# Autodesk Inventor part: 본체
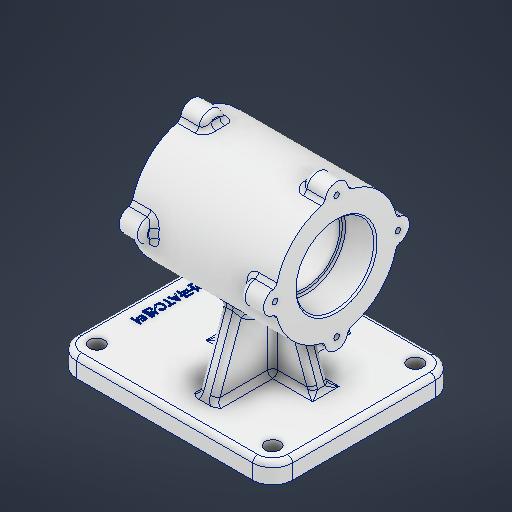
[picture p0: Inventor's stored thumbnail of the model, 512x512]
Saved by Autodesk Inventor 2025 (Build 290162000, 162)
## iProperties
Created: 2025-08
Part Number: 본체
Material: 알루미늄 6061
Document SubType Name: Modeling
Designer: infra006
Density: 2.7 g/cm^3
Appearance: 알루미늄 - 평지
Mass: 1231.61 g
Surface Area: 805.324 cm^2
Volume: 456.153 cm^3
Author: infra006
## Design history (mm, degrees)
sketch "스케치1"
  geometry: L1 (-43.5, 0)-(43.5, 0); L2 (43.5, 0)-(43.5, 23.5); L3 (43.5, 23.5)-(-43.5, 23.5); L4 (-43.5, 23.5)-(-43.5, 0); L5 (-43.5, 0)-(-24.5, 0); L6 (-24.5, 0)-(-24.5, 23.5); L7 (-24.5, 23.5)-(-43.5, 23.5); L8 (-43.5, 23.5)-(-43.5, 0); L9 (43.5, 0)-(24.5, 0); L10 (24.5, 0)-(24.5, 23.5); L11 (24.5, 23.5)-(43.5, 23.5); L12 (43.5, 23.5)-(43.5, 0); L13 (24.5, 0)-(-24.5, 0); L14 (-24.5, 0)-(-24.5, 21); L15 (-24.5, 21)-(24.5, 21); L16 (24.5, 21)-(24.5, 0); L17 (-43.5, 0)-(43.5, 0); L18 (43.5, 0)-(43.5, 37); L19 (43.5, 37)-(-43.5, 37); L20 (-43.5, 37)-(-43.5, 0); 6 further points
  constraints: 40 end point, 10 parallel, 5 horizontal, 5 perpendicular, 2 point on line, 1 coincident, 1 midpoint
  dimensions: "d1" = 87 distance of L3.end L2.end; "d2" = 19 distance of L7.end L6.end; "d3" = 23.5 distance of L6.end L5.end; "d4" = 23.5 distance of L1.end L2.end; "d5" = 19 distance of L10.end L11.end; "d6" = 21 distance of L13.end L14.end; "d7" = 37 distance of L18.end L17.end
revolve "회전1" sketch "스케치1" stored, may be unused: angle "d9" = 90 deg
sketch "스케치2"
  geometry: L1 (0, 0)-(0, -82); L2 (0, -82)-(60, -82); L3 (0, -82)-(-70, -82); L4 (-70, -82)-(-70, -70); L5 (-70, -70)-(60, -70); L6 (60, -70)-(60, -82)
  constraints: 12 end point, 2 horizontal, 2 perpendicular, 2 vertical
  dimensions: "d10" = 82 distance of L1.start L1.end; "d11" = 60 distance of L1.end L2.end; "d12" = 70 distance of L1.end L3.end; "d13" = 12 distance of L3.end L4.end
extrude "돌출1" join sketch "스케치2" stored distance "d14" = 110; taper "d15" = 0 deg
sketch "스케치3"
  geometry: L1 (0, 0)-(0, 110) reference; L2 (0, 0)-(130, 0) reference; L3 (130, 110)-(0, 110) reference; L4 (12, 98)-(118, 98); L5 (118, 98)-(118, 12); L6 (118, 12)-(12, 12); L7 (12, 12)-(12, 98)
  constraints: 8 end point, 2 parallel, 1 horizontal, 1 perpendicular
  dimensions: "d20" = 106 distance between parallel lines of L5 L7; "d21" = 86 distance between parallel lines of L6 L4; "d22" = 12 distance between parallel lines of L1 L7; "d23" = 12 distance between parallel lines of L3 L4
hole "구멍1" sketch "스케치3" at (12, 98), (12, 12), (118, 12), (118, 98) diameter "d24" = 9; stored, may be unused: countersink angle "d28" = 90 deg, drill point angle "d30" = 118 deg; dims "d25" = 6, "d26" = 4, "d27" = 2, "d29" = 12
sketch "스케치4"
  geometry: L1 (70, 50)-(80, 50); L2 (80, 50)-(80, 60); L3 (80, 60)-(70, 60); L4 (70, 60)-(70, 50); L5 (70, 50)-(80, 60); L6 (80, 50)-(70, 60); L7 (130, 110)-(130, 0) reference; L8 (130, 110)-(0, 110) reference; 1 further point
  constraints: 12 end point, 2 midpoint, 2 parallel, 1 horizontal, 1 perpendicular
  dimensions: "d31" = 10 distance of L3.end L2.end; "d32" = 10 distance of L2.end L1.end; "d125" = 55 distance from line of L7 point (75, 55); "d126" = 55 distance from line of L8 point (75, 55)
extrude "돌출2" join sketch "스케치4" stored distance "d33" = 110; taper "d34" = 0 deg
sketch "스케치5"
  geometry: L1 (0, -70)-(0, -36.661) reference; L2 (0, -70)-(-25, -70); L3 (-70, -70)-(60, -70) reference; L4 (-25, -70)-(-12.989, -37); L5 (43.5, -37)-(-43.5, -37) reference; L6 (10, -70)-(10, -36.661) reference; L7 (10, -70)-(35, -70); L8 (35, -70)-(22.989, -37); 1 further point
  constraints: 8 end point, 4 point on line
  dimensions: "d35" = 25 distance of L1.start L2.end; "d36" = 70 deg angle of L2 L4; "d37" = 25 distance of L6.start L7.end; "d38" = 70 deg angle of L8 L7; "d124" = 60 distance of L7.end L2.end (derived)
feature "리브1" dims "d39" = 1, "d40" = 10, "d41" = 0, "d42" = 0, "d43" = 1, "d44" = 1
feature "리브2" dims "d45" = 1, "d46" = 10, "d47" = 0, "d48" = 0, "d49" = 1, "d50" = 1
sketch "스케치7"
  geometry: C1 r 7 at (0, 37); C2 r 7 at (-37, 0); C3 r 7 at (0, -37); C4 r 7 at (37, 0); 10 further points
  constraints: 4 centre point, 1 horizontal alignment, 11 other
  dimensions: "d64" = 14 diameter of C1; "d67" = 360 deg dimension on point (0, 0) C1.centre (derived); "d69" = 37 distance of point (0, 0) C1.centre (derived); "d70" = 14 diameter of C2 (derived); "d71" = 37 distance of point (0, 0) C2.centre (derived)
extrude "돌출3" join sketch "스케치7" distance "d72" = 14; taper "d73" = 0 deg
sketch "스케치9"
  geometry: A1 r 37 centre (37, 0) between (0, 0) and (37, 37); 4 further points
  constraints: 4 point on circle, 2 coincident, 1 centre point
  dimensions: "d74" = 74 diameter of A1
hole "구멍3" sketch "스케치9" at (0, 0), (37, 37), (74, 0), (37, -37) diameter "d82" = 3.242; stored, may be unused: countersink angle "d86" = 90 deg, drill point angle "d88" = 118 deg; dims "d83" = 8, "d84" = 4, "d85" = 2, "d87" = 10
chamfer "모따기1" distance "d89" = 1; stored, may be unused: second distance "d90" = 2, angle "d91" = 45 deg
chamfer "모따기2" distance "d92" = 1; stored, may be unused: second distance "d93" = 2, angle "d94" = 45 deg
fillet "모깎기1" dims "d95" = 1
fillet "모깎기2" dims "d96" = 12
fillet "모깎기3" dims "d97" = 3
fillet "모깎기6" dims "d100" = 3
fillet "모깎기7" dims "d101" = 3
sketch "스케치10"
  geometry: L1 (2.821, -29.814)-(2.821, -74.186); L2 (2.821, -74.186)-(-2.821, -74.186); L3 (-2.821, -74.186)-(-2.821, -29.814); L4 (-2.821, -29.814)-(2.821, -29.814); L5 (0, -29.814)-(0, -74.186); L6 (2.821, -52)-(-2.821, -52); L7 (-12, -9)-(-12, -95) reference; L8 (118, -95)-(118, -9) reference; 4 further points
  constraints: 7 midpoint, 4 end point, 1 horizontal alignment, 1 vertical alignment, 2 other
  dimensions: "d103" = 44.37127 distance between parallel lines of L2 L4; "d116" = 118 distance from line of L5 point (118, -52); "d117" = 5.64185 distance between parallel lines of L3 L1
node "작업 평면1"
sketch "스케치12"
  geometry: L1 (-70, -55)-(-70, -41); L2 (-70, -43)-(-70, -52) reference; L3 (-70, -41)-(-26.964, -25.336); A1 r 37 centre (0, 0) between (-35.863, -9.104) and (-9.104, -35.863) reference; 1 further point
  constraints: 4 end point, 1 collinear, 1 point on circle
  dimensions: "d107" = 14 distance of L1.start L1.end; "d108" = 110 deg angle of L1 L3
feature "리브4" sketch "스케치12" dims "d109" = 1, "d110" = 10, "d111" = 0, "d112" = 0, "d113" = 1, "d114" = 1
feature "엠보싱1" dims "d1" = 87, "d2" = 19, "d3" = 23.5, "d4" = 23.5, "d5" = 19, "d6" = 21, "d7" = 37, "d118" = 0.5, "d119" = 0
fillet "모깎기10" dims "d122" = 3
fillet "모깎기11" dims "d123" = 3
node "솔리드1"
mirror "미러2"
mirror "미러3"
mirror "미러4"
mirror "미러5"
node "스케치 - 원형 패턴1" dims "d67" = 360 deg (derived)
feature "A9D066F2-1C7D-4E18-AEED-F7BC21143FA4" dims "d24" = 9, "d25" = 6, "d26" = 4, "d27" = 2, "d28" = 90 deg, "d29" = 12, "d30" = 118 deg
other parameters: "d106" = 5
